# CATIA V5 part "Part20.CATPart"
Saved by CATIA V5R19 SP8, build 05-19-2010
Part number: Lame
Bounding box of the stored display mesh (mm): x 0 to 11.519, y -386 to 398.468, z -392.667 to 396.244
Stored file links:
  G:\EU_thinkMotion\CFAO_2010\MMS_groupe1\MMS_groupe1\OK\ppiault\piault\piault_cfao\Part20.CATPart
  D:\Catia\Finaltest.CATProduct
  G:\Catia Projet\CFAO2\Product2.CATProduct
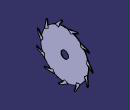
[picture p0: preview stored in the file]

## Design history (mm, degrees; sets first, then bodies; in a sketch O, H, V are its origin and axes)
External parameters (linked from other documents)
  External.DiametreScie = 330 mm
  External.Epaisseur = 5 mm
Body1 (main body)
  Plane1 to Plane5: stored without definition
  Sketch1 on yz-plane, origin (0, 0, 0), H (0, 1, 0), V (0, 0, 1)
    arc A1 centre (0, 0) radius 330 from (-276.9233, -179.4812) to (-310.9314, -110.5517) ccw
    point P1 (0, 0)
    circle A2 centre (0, 0) radius 52
    point P2 (0, 0)
    line L1 (-386, -80.6089) -> (-386, -100.6089)
    line L2 (-386, -100.6089) -> (-276.9233, -179.4812)
    line L3 (-386, -80.6089) -> (-310.9314, -110.5517)
    reference intersected line E1 through (0, 0) direction (0, 1) from Plane3
    reference intersected line E2 through (0, 0) direction (0, 1) from Plane5
    radius A2 = 52
    radius A1 = 330 {= External.DiametreScie}
    distance L1 E2 = 386 {= 386/330*External.DiametreScie}
    length L1 = 20
    coincidence: P2 P1, O P2
    parallelism: E1 L1
    vertical: L1 V
  Pad1: profile Sketch1, direction (1, 0, 0), length 6 {= 6/5*External.Epaisseur}
  Sketch2 on face of Pad1 from Sketch1.L2, origin (0, -184.8507, -246.0579), H (1, 0, 0), V (0, -0.8103, 0.586)
    line L1 (0, 113.6214) -> (6, 259.9457)
    point P1 (0, 113.6214)
    point P2 (6, 259.9457)
    line L2 (6, 259.9457) -> (0, 259.9457)
    line L3 (0, 259.9457) -> (0, 113.6214)
    reference projected line E1 (0, 289.2113) -> (0, 208.6796) from edge [start face of Pad1 | face of Pad1 from Sketch1.L2]
    reference projected line E2 (0, 259.9457) -> (12, 259.9457) from edge [face of Pad1 from Sketch1.L1 | face of Pad1 from Sketch1.L3]
    reference intersected line E3 (6, 289.2113) -> (6, -208.6796) from end face of Pad1
    reference projected line E4 (0, 113.6214) -> (12, 113.6214) from edge [face of Pad1 from Sketch1.A1 | face of Pad1 from Sketch1.L2]
    horizontal: L2 H
    coincidence: E1 L3, E2 L2, E3 P2, E4 P1
  Pocket1: profile Sketch2, direction along edge [start face of Pad1 | face of Pad1 from Sketch1.L1] reversed, length 45
  Sketch3 on face of Pad1 from Sketch1.L2, origin (0, -184.8507, -246.0579), H (1, 0, 0), V (0, -0.8103, 0.586)
    line L1 (6, 248.2266) -> (6, 113.6214)
    point P2 (6, 113.6214)
    line L2 (6, 248.2266) -> (11.5195, 248.2266)
    line L3 (6, 113.6214) -> (11.5195, 248.2266)
    reference projected line E1 (6, 289.2113) -> (6, 208.6796) from edge [face of Pad1 from Sketch1.L2 | end face of Pad1]
    reference projected line E2 (0, 113.6214) -> (12, 113.6214) from edge [face of Pad1 from Sketch1.A1 | face of Pad1 from Sketch1.L2]
    reference projected line E3 (3.8696, 207.9909) -> (7.1966, 289.1284) from edge [face of Pad1 from Sketch1.L2 | face of Pocket1 from Sketch2.L1]
    reference projected line E4 (0, 248.2266) -> (12, 248.2266) from edge [face of Pad1 from Sketch1.L2 | face of Pad1 from Sketch1.L1]
    coincidence: E1 L1, E2 P2, E4 L2
    parallelism: E3 L3
  Pad2: profile Sketch3, direction along edge [face of Pad1 from Sketch1.L1 | end face of Pad1] reversed, up to face of Pad1 from Sketch1.L3
  Sketch4 on face of Pad2, origin (0, -386, 0), H (1, 0, 0), V (0, 0, 1)
    line L1 (5.5195, -80.6089) -> (11.5195, -80.6089)
    line L2 (11.5195, -80.6089) -> (11.5195, -90.6089)
    line L3 (5.5195, -90.6089) -> (5.5195, -80.6089)
    line L4 (5.5195, -90.6089) -> (8.5195, -80.7089)
    point P3 (5.5195, -90.6089)
    point P4 (8.5195, -80.7089)
    line L5 (11.5195, -90.6089) -> (8.5195, -80.7089)
    point P5 (11.5195, -90.6089)
    reference projected line E1 (5.5195, -111.7053) -> (5.5195, -91.7053) from edge [face of Pad2 | face of Pocket1 from Sketch2.L1]
    reference projected line E2 (11.5195, -111.7053) -> (11.5195, -91.7053) from edge [face of Pad2 from Sketch3.L3 | face of Pad2]
    reference projected line E3 (0, -100.6089) -> (6, -100.6089) from edge [face of Pad2 | face of Pad2]
    reference projected line E4 (0, -100.6089) -> (6, -100.6089) from edge [face of Pad2 | face of Pad2]
    reference projected line E5 (6, -80.6089) -> (0, -80.6089) from edge [face of Pad1 | face of Pad1]
    distance E3 P5 = 10
    distance E4 P3 = 10
    distance L1 P4 = 0.1
    distance P4 L2 = 3
    horizontal: L1 H
    vertical: L2 V, L3 V
    coincidence: E1 L3, E2 L2, E5 L1
  Pocket2: profile Sketch4, direction along edge [face of Pad1 | face of Pocket1 from Sketch2.L1], length 83
  Fillet1: radius 2, on edge [face of Pad2 | face of Pad2]
  Chamfer1: length 1, angle 45, on edge [start face of Pad1 | face of Pocket2]
  Line1: stored without definition
  CircPattern1: of the body so far, instances 12, angular step 32.7273, axis from start face of Pad1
